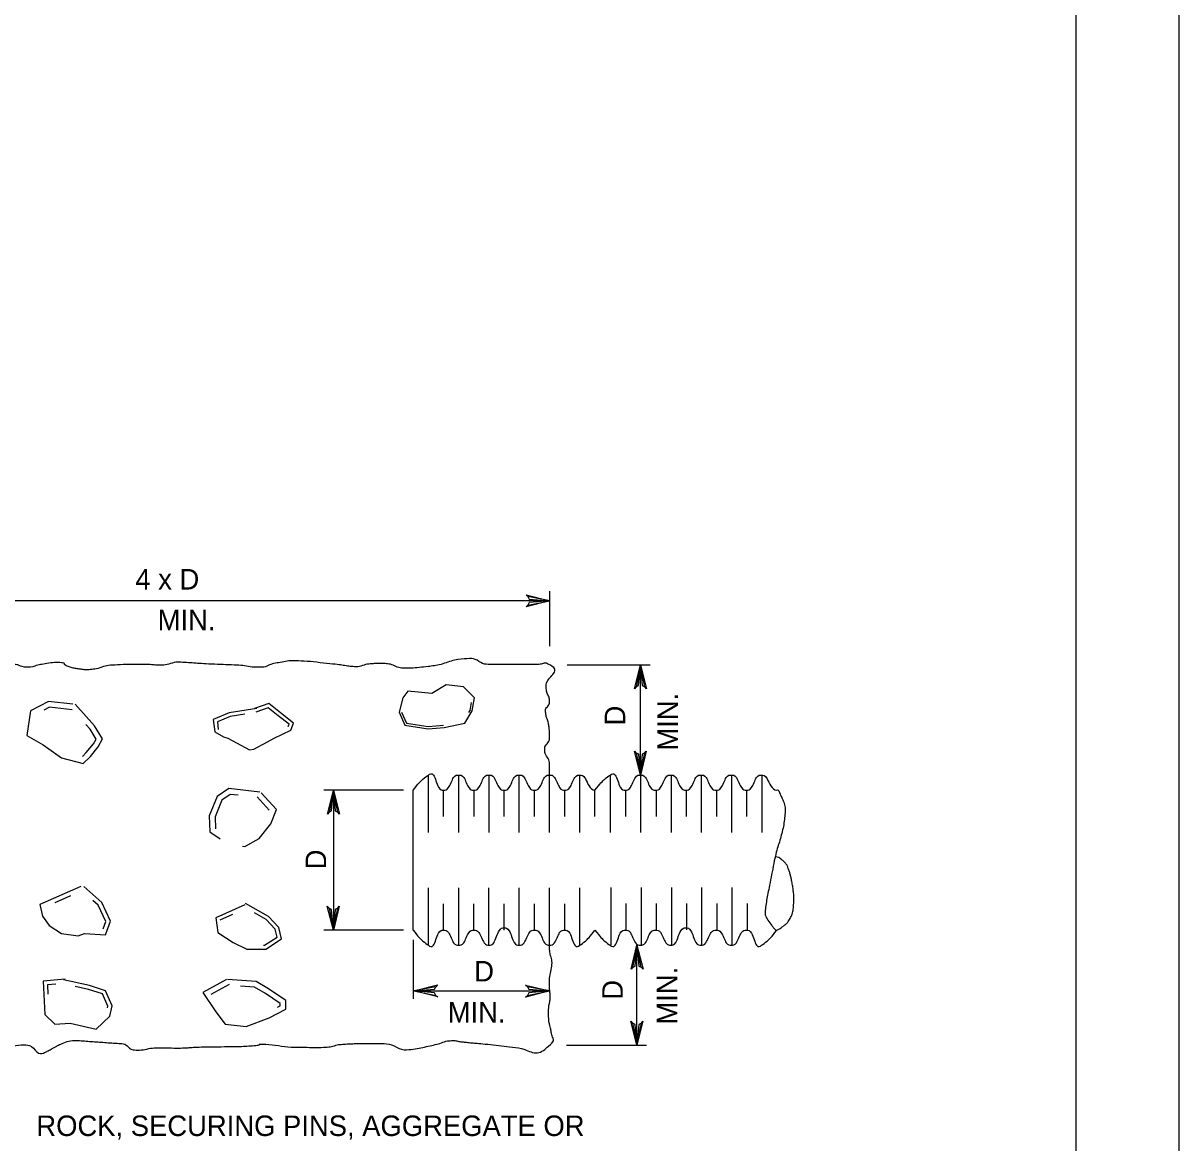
# Model space of a CAD drawing. Extents: x 636462 to 637367, y 299944 to 300538.
# Drawn here: x 637133.8 to 637302.9, y 300210.9 to 300374.7 of the extents above; entities that cross this region are included whole.
import ezdxf

# ---------------------------------------------------------------- set-up
doc = ezdxf.new("R2010")
doc.units = 0
for name, color, linetype in [('1', 7, 'Continuous'), ('Default', 7, 'Continuous'), ('PLT-BNDY', 7, 'Continuous')]:
    doc.layers.add(name, color=color, linetype=linetype)

# ---------------------------------------------------------------- blocks, each defined once
blk = doc.blocks.new('SC9446')
at = {"layer": 'Default'}
blk.add_line((0, 0), (0, 0), dxfattribs=at)

msp = doc.modelspace()

# ---------------------------------------------------------------- linework, layer by layer
at = {"layer": '1'}
msp.add_lwpolyline([(637287.91, 299959.45), (637287.91, 300523.45), (636501.91, 300523.45), (636501.91, 299959.45), (637287.91, 299959.45), (637287.91, 299985.81), (637087.91, 299985.81), (637087.91, 300050.49), (637287.91, 300050.49), (637287.91, 300079.45), (637087.91, 300079.45), (637087.91, 299959.45), (637166.72, 299959.45), (637166.72, 299985.81), (637166.72, 299959.45), (637243.72, 299959.45), (637243.72, 299985.81), (637243.72, 299973.49), (637287.91, 299973.49)], dxfattribs=at)
at = {"layer": 'Default'}
for p, q in [((637210.91, 300283.57), (637210.91, 300291.6)), ((637210.91, 300290.19), (637109.32, 300290.19)), ((637213.45, 300280.83), (637225.56, 300280.83)), ((637224.15, 300264.71), (637224.15, 300280.83)), ((637199.04, 300273.87), (637199.27, 300274.26)), ((637199.24, 300274.16), (637199.43, 300275.33)), ((637193.13, 300256.29), (637193.13, 300264.71)), ((637197.56, 300256.29), (637197.56, 300264.71)), ((637201.99, 300264.71), (637201.99, 300256.29)), ((637206.42, 300256.29), (637206.42, 300264.71)), ((637210.85, 300256.29), (637210.85, 300264.71)), ((637215.29, 300256.29), (637215.29, 300264.71)), ((637219.79, 300256.3), (637219.79, 300264.72)), ((637224.22, 300256.3), (637224.22, 300264.72)), ((637228.65, 300264.72), (637228.65, 300256.3)), ((637233.08, 300256.3), (637233.08, 300264.72)), ((637237.51, 300256.3), (637237.51, 300264.72)), ((637241.95, 300256.3), (637241.95, 300264.72)), ((637189.5, 300262.49), (637177.82, 300262.49)), ((637179.23, 300262.49), (637179.23, 300242.02)), ((637190.91, 300242.02), (637190.91, 300262.49)), ((637195.35, 300258.63), (637195.35, 300262.49)), ((637199.78, 300262.49), (637199.78, 300258.63)), ((637204.21, 300258.63), (637204.21, 300262.49)), ((637208.64, 300258.63), (637208.64, 300262.49)), ((637213.07, 300258.63), (637213.07, 300262.49)), ((637217.5, 300258.63), (637217.5, 300262.49)), ((637222, 300258.64), (637222, 300262.5)), ((637226.43, 300262.5), (637226.43, 300258.64)), ((637230.87, 300258.64), (637230.87, 300262.5)), ((637235.3, 300258.64), (637235.3, 300262.5)), ((637239.73, 300258.64), (637239.73, 300262.5)), ((637169.86, 300259.58), (637168.08, 300261.54)), ((637140.77, 300247.02), (637138.47, 300246.02)), ((637193.13, 300239.81), (637193.13, 300248.23)), ((637197.56, 300239.81), (637197.56, 300248.23)), ((637201.99, 300239.81), (637201.99, 300248.23)), ((637206.42, 300242.58), (637206.42, 300248.23)), ((637206.42, 300239.81), (637206.42, 300248.23)), ((637210.85, 300242.32), (637210.85, 300248.23)), ((637210.85, 300239.81), (637210.85, 300248.23)), ((637215.29, 300239.81), (637215.29, 300248.23)), ((637219.86, 300239.86), (637219.86, 300248.28)), ((637224.29, 300239.86), (637224.29, 300248.28)), ((637228.72, 300239.86), (637228.72, 300248.28)), ((637233.15, 300242.63), (637233.15, 300248.28)), ((637233.15, 300239.86), (637233.15, 300248.28)), ((637237.58, 300242.37), (637237.58, 300248.28)), ((637237.58, 300239.86), (637237.58, 300248.28)), ((637195.35, 300242.02), (637195.35, 300245.89)), ((637199.78, 300242.02), (637199.78, 300245.89)), ((637204.21, 300242.35), (637204.21, 300245.89)), ((637204.21, 300242.02), (637204.21, 300245.89)), ((637208.64, 300242.83), (637208.64, 300245.89)), ((637208.64, 300242.02), (637208.64, 300245.89)), ((637213.07, 300242.02), (637213.07, 300245.89)), ((637222.07, 300242.07), (637222.07, 300245.93)), ((637226.5, 300242.07), (637226.5, 300245.93)), ((637230.94, 300242.4), (637230.94, 300245.94)), ((637230.94, 300242.07), (637230.94, 300245.94)), ((637235.37, 300242.88), (637235.37, 300245.94)), ((637235.37, 300242.07), (637235.37, 300245.94)), ((637239.8, 300242.07), (637239.8, 300245.93)), ((637164.48, 300244.29), (637162.64, 300243.46)), ((637189.5, 300242.02), (637177.82, 300242.02)), ((637190.91, 300240.61), (637190.91, 300231.96)), ((637223.64, 300236.16), (637223.64, 300239.81)), ((637223.64, 300225.19), (637223.64, 300239.8)), ((637164.01, 300234.08), (637161.3, 300232.61)), ((637190.98, 300233.12), (637210.84, 300233.12)), ((637213.35, 300225.19), (637225.05, 300225.19))]:
    msp.add_line(p, q, dxfattribs=at)
for points in [[(637207.68, 300290.83), (637207.41, 300291.05), (637210.91, 300290.19), (637207.68, 300290.83), (637207.88, 300290.45), (637210.91, 300290.19), (637207.88, 300289.93), (637207.7, 300289.55), (637210.91, 300290.19), (637207.42, 300289.3), (637207.7, 300289.55)], [(637223.51, 300277.59), (637223.29, 300277.32), (637224.15, 300280.83), (637223.51, 300277.59), (637223.88, 300277.79), (637224.15, 300280.83), (637224.41, 300277.8), (637224.78, 300277.61), (637224.15, 300280.83), (637225.04, 300277.33), (637224.78, 300277.61)], [(637199.54, 300274.11), (637199.86, 300276.01), (637198.27, 300277.6), (637195.73, 300277.92), (637193.62, 300276.65), (637190.13, 300276.96), (637189.39, 300276.01), (637188.86, 300273.9), (637189.7, 300271.99), (637193.09, 300271.46), (637195.42, 300271.67), (637198.48, 300272.31), (637199.54, 300274.11)], [(637141.14, 300275.06), (637137.54, 300275.48), (637134.9, 300274.11), (637134.37, 300270.51), (637136.8, 300269.13), (637139.44, 300267.23), (637142.62, 300266.38), (637143.68, 300267.44), (637144.84, 300268.82), (637145.48, 300269.98), (637144.31, 300271.89), (637141.46, 300275.06)], [(637141.04, 300274.25), (637137.7, 300274.64), (637136.86, 300274.21)], [(637168.01, 300274.42), (637163.99, 300273.79), (637161.66, 300272.84), (637161.88, 300271.04), (637163.15, 300270.3), (637163.78, 300270.09), (637166.95, 300268.39), (637167.59, 300268.5), (637169.6, 300269.56), (637170.55, 300270.09), (637172.99, 300271.25), (637173.41, 300272.31), (637171.5, 300273.79), (637169.81, 300275.17), (637167.7, 300274.42)], [(637172.62, 300271.82), (637172.75, 300272.13), (637171.16, 300273.36), (637169.7, 300274.55), (637167.88, 300273.91)], [(637166.3, 300273.6), (637164.14, 300273.26), (637162.26, 300272.49), (637162.39, 300271.37)], [(637189.18, 300273.92), (637189.92, 300272.27), (637193.1, 300271.78), (637195.32, 300271.98)], [(637142.52, 300267.44), (637143.08, 300268), (637144.16, 300269.28), (637144.53, 300269.96), (637143.65, 300271.39), (637143.03, 300272.09)], [(637224.79, 300267.94), (637225.01, 300268.21), (637224.15, 300264.71), (637224.79, 300267.94), (637224.41, 300267.74), (637224.15, 300264.71), (637223.89, 300267.74), (637223.51, 300267.92), (637224.15, 300264.71), (637223.26, 300268.2), (637223.51, 300267.92)], [(637168.48, 300262.21), (637163.93, 300262.74), (637162.24, 300261.58), (637161.08, 300258.72), (637161.18, 300256.39), (637162.67, 300255.38)], [(637178.59, 300259.26), (637178.37, 300258.99), (637179.23, 300262.49), (637178.59, 300259.26), (637178.96, 300259.46), (637179.23, 300262.49), (637179.49, 300259.46), (637179.86, 300259.28), (637179.23, 300262.49), (637180.12, 300259), (637179.86, 300259.28)], [(637165.3, 300261.74), (637164.15, 300261.87), (637162.92, 300261.03), (637161.92, 300258.57), (637162, 300256.85)], [(637165.92, 300254.32), (637166.26, 300254.27), (637168.38, 300255.44), (637170.07, 300257.55), (637170.92, 300259.67), (637168.69, 300262.1)], [(637142.3, 300248.4), (637136.27, 300245.75), (637136.7, 300244.06), (637137.65, 300242.68), (637139.44, 300241.52), (637141.88, 300241.2), (637142.83, 300241.52), (637145.9, 300241.31), (637146.64, 300243.32), (637145.37, 300246.07), (637142.73, 300248.4)], [(637145.55, 300242.21), (637145.94, 300243.29), (637144.84, 300245.68), (637144.06, 300246.37)], [(637166.26, 300245.7), (637162.03, 300243.8), (637162.35, 300241.68), (637164.57, 300240.2), (637166.58, 300239.25), (637169.33, 300239.25), (637171.66, 300240.73), (637171.23, 300242.42), (637169.75, 300244.01), (637166.37, 300245.92)], [(637179.86, 300245.25), (637180.09, 300245.52), (637179.23, 300242.02), (637179.86, 300245.25), (637179.49, 300245.06), (637179.23, 300242.02), (637178.97, 300245.05), (637178.59, 300245.23), (637179.23, 300242.02), (637178.34, 300245.52), (637178.59, 300245.23)], [(637169.01, 300239.81), (637169.17, 300239.81), (637171.02, 300240.99), (637170.73, 300242.15), (637169.4, 300243.57), (637167.68, 300244.54)], [(637223, 300236.57), (637222.78, 300236.3), (637223.64, 300239.8), (637223, 300236.57), (637223.38, 300236.77), (637223.64, 300239.8), (637223.9, 300236.77), (637224.27, 300236.59), (637223.64, 300239.8), (637224.53, 300236.31), (637224.27, 300236.59)], [(637139.98, 300234.85), (637136.8, 300234.54), (637137.01, 300229.67), (637138.49, 300228.29), (637140.72, 300228.4), (637144.52, 300227.55), (637146.53, 300229.46), (637146.85, 300230.94), (637145.9, 300233.16), (637143.57, 300233.9), (637139.76, 300234.75)], [(637138.63, 300234.13), (637137.41, 300234.01), (637137.47, 300232.64)], [(637146.2, 300230.66), (637146.24, 300230.88), (637145.47, 300232.69), (637143.42, 300233.34), (637141.47, 300233.77)], [(637163.61, 300234.81), (637160.12, 300232.9), (637162.03, 300230.05), (637163.4, 300228.25), (637166.47, 300227.93), (637169.86, 300229.2), (637172.29, 300230.47), (637172.29, 300231.74), (637169.75, 300233.43), (637167.95, 300234.49), (637163.72, 300234.81)], [(637171.04, 300230.74), (637171.47, 300230.97), (637171.47, 300231.3), (637169.32, 300232.73), (637167.7, 300233.68), (637165.62, 300233.84)], [(637194.22, 300232.48), (637194.49, 300232.26), (637190.98, 300233.12), (637194.22, 300232.48), (637194.02, 300232.85), (637190.98, 300233.12), (637194.01, 300233.38), (637194.2, 300233.75), (637190.98, 300233.12), (637194.48, 300234.01), (637194.2, 300233.75)], [(637207.61, 300233.75), (637207.34, 300233.98), (637210.84, 300233.12), (637207.61, 300233.75), (637207.8, 300233.38), (637210.84, 300233.12), (637207.81, 300232.86), (637207.63, 300232.48), (637210.84, 300233.12), (637207.34, 300232.23), (637207.63, 300232.48)], [(637224.28, 300228.42), (637224.5, 300228.69), (637223.64, 300225.19), (637224.28, 300228.42), (637223.9, 300228.23), (637223.64, 300225.19), (637223.38, 300228.22), (637223.01, 300228.4), (637223.64, 300225.19), (637222.75, 300228.69), (637223.01, 300228.4)]]:
    msp.add_lwpolyline(points, dxfattribs=at)
for points in [[(637134.44, 300280.46), (637133.82, 300280.45), (637133.22, 300280.82), (637132.59, 300280.88), (637132.01, 300280.93), (637131.43, 300280.98), (637130.85, 300280.98), (637129.53, 300280.99), (637128.22, 300280.9), (637126.91, 300280.77), (637125.99, 300280.69), (637125.14, 300280.16), (637124.24, 300280.14), (637123.62, 300280.12), (637123.01, 300280.44), (637122.38, 300280.46), (637121.61, 300280.48), (637120.84, 300280.43), (637120.06, 300280.46), (637118.6, 300280.51), (637117.13, 300280.73), (637115.66, 300280.77), (637114.62, 300280.8), (637113.57, 300280.61), (637112.53, 300280.56), (637111.46, 300280.51), (637110.39, 300281.42), (637109.32, 300280.82), (637108.5, 300280.36), (637109.48, 300279.24), (637109.28, 300278.55), (637109.17, 300278.16), (637108.74, 300277.78), (637108.7, 300277.39), (637108.65, 300276.83), (637109.4, 300276.29), (637109.4, 300275.7), (637109.39, 300274.53), (637108.75, 300273.37), (637108.82, 300272.2), (637108.88, 300271.29), (637109.33, 300270.37), (637109.28, 300269.45), (637109.26, 300269), (637109.19, 300268.54), (637109.17, 300268.08), (637109.11, 300266.81), (637109.07, 300265.54), (637109.05, 300264.27), (637109.04, 300263.32), (637109.17, 300262.36), (637109.17, 300261.41), (637109.17, 300260.81), (637108.95, 300260.21), (637108.94, 300259.61), (637108.91, 300258.66), (637109.18, 300257.71), (637109.17, 300256.76), (637109.15, 300255.63), (637108.84, 300254.5), (637108.82, 300253.37), (637108.81, 300252.59), (637109.07, 300251.82), (637109.05, 300251.04), (637109.04, 300250.48), (637108.84, 300249.91), (637108.82, 300249.35), (637108.76, 300248.05), (637109.11, 300246.73), (637109.05, 300245.43), (637109.03, 300244.86), (637108.73, 300244.31), (637108.7, 300243.74), (637108.65, 300242.58), (637109.09, 300241.41), (637109.05, 300240.25), (637109.02, 300239.23), (637108.53, 300238.21), (637108.59, 300237.18), (637108.7, 300235.21), (637109.17, 300233.24), (637109.28, 300231.26), (637109.34, 300230.34), (637109.36, 300229.42), (637109.4, 300228.51), (637109.44, 300227.4), (637108.56, 300226.3), (637109.32, 300225.19), (637109.81, 300224.48), (637110.86, 300225.81), (637111.6, 300225.65), (637112.38, 300225.48), (637113.12, 300225), (637113.92, 300224.91), (637115.9, 300224.69), (637117.96, 300224.62), (637119.95, 300224.7), (637121.54, 300224.76), (637123.13, 300225.58), (637124.7, 300225.44)], [(637210.86, 300264.71), (637210.86, 300265.2), (637210.85, 300265.68), (637210.85, 300266.17), (637210.84, 300266.94), (637210.18, 300267.66), (637210.15, 300268.39), (637210.13, 300269), (637210.83, 300269.58), (637210.85, 300270.19), (637210.86, 300270.77), (637210.82, 300271.4), (637210.73, 300271.99), (637210.64, 300272.63), (637210.34, 300273.27), (637210.27, 300273.9), (637210.21, 300274.43), (637210.86, 300274.95), (637210.85, 300275.48), (637210.84, 300276.08), (637210.46, 300276.68), (637210.38, 300277.28), (637210.24, 300278.44), (637212.17, 300280.07), (637210.86, 300280.82), (637210.24, 300281.19), (637209.62, 300280.88), (637208.99, 300280.88), (637207.91, 300280.88), (637206.83, 300280.88), (637205.75, 300280.88), (637204.55, 300280.88), (637203.35, 300280.88), (637202.15, 300280.88), (637201.03, 300280.88), (637200, 300281.77), (637198.91, 300281.73), (637196.95, 300281.65), (637194.98, 300280.79), (637192.99, 300280.56), (637191.81, 300280.43), (637190.58, 300280.29), (637189.4, 300280.35), (637188.57, 300280.39), (637187.8, 300280.92), (637186.96, 300280.98), (637186.28, 300281.04), (637185.56, 300281.03), (637184.88, 300280.98), (637183.95, 300280.92), (637183.03, 300280.49), (637182.1, 300280.56), (637181.28, 300280.62), (637180.47, 300280.79), (637179.66, 300280.88), (637177.77, 300281.08), (637175.87, 300281.31), (637173.98, 300281.41), (637172.97, 300281.46), (637171.97, 300281.25), (637170.96, 300281.09), (637170.09, 300280.95), (637169.29, 300280.46), (637168.41, 300280.46), (637167.34, 300280.46), (637166.25, 300280.72), (637165.17, 300280.77), (637163.51, 300280.85), (637161.84, 300280.91), (637160.18, 300280.98), (637159.1, 300281.04), (637158.02, 300281.15), (637156.94, 300281.2), (637155.92, 300281.24), (637154.93, 300280.77), (637153.92, 300280.77), (637153.19, 300280.77), (637152.45, 300280.87), (637151.72, 300280.88), (637150.09, 300280.9), (637148.47, 300280.87), (637146.85, 300280.77), (637145.82, 300280.71), (637144.85, 300280.24), (637143.83, 300280.14), (637143.15, 300280.07), (637142.44, 300280.15), (637141.75, 300280.24), (637141.14, 300280.33), (637140.56, 300280.53), (637140.01, 300280.77), (637139.88, 300280.83), (637139.91, 300281.07), (637139.78, 300281.09), (637138.72, 300281.22), (637137.59, 300281.05), (637136.53, 300280.88), (637135.83, 300280.77), (637135.14, 300280.46), (637134.44, 300280.46)], [(637190.91, 300262.49), (637191.65, 300263.48), (637192.39, 300264.19), (637193.13, 300264.71), (637193.87, 300265.23), (637194.61, 300262.49), (637195.35, 300262.49), (637196.08, 300262.49), (637196.82, 300264.71), (637197.56, 300264.71), (637198.3, 300264.71), (637199.04, 300262.49), (637199.78, 300262.49), (637200.51, 300262.49), (637201.25, 300264.71), (637201.99, 300264.71), (637202.73, 300264.71), (637203.47, 300262.49), (637204.21, 300262.49), (637204.95, 300262.49), (637205.68, 300264.71), (637206.42, 300264.71), (637207.16, 300264.71), (637207.9, 300262.49), (637208.64, 300262.49), (637209.38, 300262.49), (637210.12, 300264.71), (637210.85, 300264.71), (637211.59, 300264.71), (637212.33, 300262.49), (637213.07, 300262.49), (637213.81, 300262.49), (637214.55, 300264.71), (637215.29, 300264.71), (637216.03, 300264.71), (637216.76, 300262.49), (637217.5, 300262.49)], [(637217.5, 300262.49), (637218.24, 300263.48), (637218.98, 300264.18), (637219.72, 300264.71), (637220.46, 300265.23), (637221.19, 300262.49), (637221.93, 300262.49), (637222.67, 300262.49), (637223.41, 300264.71), (637224.15, 300264.71), (637224.89, 300264.71), (637225.62, 300262.49), (637226.36, 300262.49), (637227.1, 300262.49), (637227.84, 300264.71), (637228.58, 300264.71), (637229.32, 300264.71), (637230.06, 300262.49), (637230.79, 300262.49), (637231.53, 300262.49), (637232.27, 300264.71), (637233.01, 300264.71), (637233.75, 300264.71), (637234.49, 300262.49), (637235.23, 300262.49), (637235.97, 300262.49), (637236.7, 300264.71), (637237.44, 300264.71), (637238.18, 300264.71), (637238.92, 300262.49), (637239.66, 300262.49), (637240.4, 300262.49), (637241.14, 300264.71), (637241.87, 300264.71), (637242.61, 300264.71), (637243.35, 300262.49), (637244.09, 300262.49)], [(637244.09, 300262.49), (637244.3, 300262.69), (637244.66, 300261.77), (637244.86, 300261.3), (637245.2, 300260.53), (637245.35, 300259.75), (637245.28, 300258.98), (637245.19, 300257.95), (637245.02, 300256.93), (637244.75, 300255.91), (637244.49, 300254.9), (637244.12, 300253.95), (637243.91, 300252.94), (637243.56, 300251.36), (637243.27, 300249.77), (637242.95, 300248.18), (637242.75, 300247.16), (637242.56, 300246.14), (637242.43, 300245.12), (637242.31, 300244.26), (637242.78, 300243.48), (637243.38, 300242.68), (637243.6, 300242.38), (637243.84, 300242.07), (637244.09, 300242.02)], [(637244.09, 300242.02), (637244.38, 300242.14), (637244.61, 300242.29), (637244.86, 300242.47), (637245.27, 300242.78), (637245.64, 300243.07), (637245.92, 300243.53), (637246.33, 300244.2), (637246.49, 300244.91), (637246.55, 300245.65), (637246.6, 300246.24), (637246.62, 300246.85), (637246.55, 300247.45), (637246.48, 300248.12), (637246.37, 300248.79), (637246.23, 300249.45), (637246.13, 300249.96), (637245.99, 300250.45), (637245.81, 300250.94), (637245.65, 300251.37), (637245.46, 300251.73), (637245.07, 300252.1), (637244.69, 300252.45), (637244.3, 300252.73), (637243.91, 300252.74)], [(637190.91, 300242.02), (637191.65, 300241.04), (637192.39, 300240.33), (637193.13, 300239.81), (637193.87, 300239.28), (637194.61, 300242.02), (637195.35, 300242.02), (637196.08, 300242.02), (637196.82, 300239.81), (637197.56, 300239.81), (637198.3, 300239.81), (637199.04, 300242.01), (637199.78, 300242.02), (637200.51, 300242.04), (637201.31, 300239.81), (637201.99, 300239.81), (637202.73, 300239.81), (637203.47, 300242.35), (637204.21, 300242.35), (637204.95, 300242.35), (637205.66, 300239.81), (637206.42, 300239.81), (637207.14, 300239.81), (637207.9, 300242.04), (637208.64, 300242.02), (637209.38, 300242.01), (637210.12, 300239.81), (637210.85, 300239.81), (637211.59, 300239.81), (637212.33, 300242.02), (637213.07, 300242.02), (637213.81, 300242.02), (637214.55, 300239.28), (637215.29, 300239.81), (637216.03, 300240.33), (637216.76, 300241.04), (637217.5, 300242.02)], [(637217.5, 300242.02), (637218.24, 300241.04), (637218.98, 300240.33), (637219.72, 300239.81), (637220.46, 300239.28), (637221.19, 300242.02), (637221.93, 300242.02), (637222.67, 300242.02), (637223.41, 300239.81), (637224.15, 300239.81), (637224.89, 300239.81), (637225.62, 300242.01), (637226.36, 300242.02), (637227.1, 300242.04), (637227.89, 300239.81), (637228.58, 300239.81), (637229.32, 300239.81), (637230.06, 300242.35), (637230.79, 300242.35), (637231.53, 300242.35), (637232.24, 300239.81), (637233.01, 300239.81), (637233.72, 300239.81), (637234.49, 300242.04), (637235.23, 300242.02), (637235.97, 300242.01), (637236.7, 300239.81), (637237.44, 300239.81), (637238.18, 300239.81), (637238.92, 300242.02), (637239.66, 300242.02), (637240.4, 300242.02), (637241.14, 300239.28), (637241.87, 300239.81), (637242.61, 300240.33), (637243.35, 300241.04), (637244.09, 300242.02)], [(637210.73, 300229.03), (637210.7, 300229.56), (637210.7, 300230.1), (637210.73, 300230.62), (637210.77, 300231.15), (637210.94, 300231.68), (637210.94, 300232.21), (637210.94, 300232.77), (637210.84, 300233.34), (637210.84, 300233.9), (637210.84, 300234.32), (637210.84, 300234.75), (637210.84, 300235.17), (637211.47, 300237.8), (637210.84, 300238.26), (637210.85, 300239.81)], [(637124.7, 300225.44), (637125.1, 300225.4), (637125.46, 300225.19), (637125.86, 300225.12), (637126.98, 300224.92), (637128.1, 300224.77), (637129.22, 300224.7), (637130.81, 300224.59), (637132.4, 300225.21), (637133.98, 300225.23), (637135.08, 300225.24), (637136.13, 300223.7), (637137.11, 300224.17), (637137.38, 300224.3), (637137.65, 300224.45), (637137.92, 300224.59), (637138.31, 300224.8), (637138.68, 300225.02), (637139.08, 300225.23), (637140, 300225.69), (637141.07, 300225.93), (637142.09, 300225.86), (637143.06, 300225.79), (637144.03, 300225.72), (637144.99, 300225.65), (637146.04, 300225.58), (637147.08, 300225.51), (637148.12, 300225.44), (637148.93, 300225.38), (637149.52, 300224.5), (637150.33, 300224.49), (637151.4, 300224.47), (637152.48, 300224.79), (637153.57, 300224.8), (637154.89, 300224.82), (637156.2, 300224.75), (637157.52, 300224.8), (637158.13, 300224.83), (637158.75, 300224.89), (637159.37, 300224.91), (637161.34, 300224.98), (637163.31, 300224.97), (637165.28, 300225.01), (637166.33, 300225.04), (637167.37, 300225.11), (637168.41, 300225.23), (637168.45, 300225.23), (637168.37, 300225.33), (637168.41, 300225.33), (637170.26, 300225.34), (637172.12, 300224.93), (637173.98, 300224.91), (637175.37, 300224.89), (637176.77, 300224.82), (637178.15, 300224.91), (637178.98, 300224.96), (637179.76, 300225.28), (637180.59, 300225.33), (637181.44, 300225.39), (637182.29, 300225.42), (637183.14, 300225.44), (637184.18, 300225.46), (637185.24, 300225.46), (637186.27, 300225.44), (637187.75, 300225.41), (637189.21, 300224.4), (637190.67, 300224.59), (637191.76, 300224.73), (637192.84, 300224.99), (637193.92, 300225.23), (637194.82, 300225.42), (637195.68, 300225.83), (637196.59, 300225.86), (637197.16, 300225.88), (637197.74, 300225.7), (637198.33, 300225.65), (637199.1, 300225.58), (637199.87, 300225.51), (637200.65, 300225.44), (637202.23, 300225.29), (637203.81, 300225.08), (637205.4, 300224.91), (637207.21, 300224.71), (637209.08, 300223.62), (637210.86, 300225.19), (637211.6, 300225.84), (637211.18, 300226.56), (637211.08, 300227.24), (637210.99, 300227.83), (637210.77, 300228.43), (637210.73, 300229.03)]]:
    msp.add_open_spline(points, degree=3, dxfattribs=at)
at = {"layer": 'PLT-BNDY'}
msp.add_lwpolyline([(636461.91, 300538.45), (637302.91, 300538.45), (637302.91, 299944.45), (636461.91, 299944.45)], close=True, dxfattribs=at)

# ---------------------------------------------------------------- block references
at = {"layer": 'Default', "xscale": 2.2030652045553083, "yscale": 2.2030652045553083}
for p in [(637201.99, 300248.23), (637228.72, 300248.28)]:
    msp.add_blockref('SC9446', p, dxfattribs=at)

# ---------------------------------------------------------------- texts
at = {"layer": 'Default'}
for s, height, p in [('4 x D', 2.998, (637150.26, 300291.84)), ('MIN.', 2.998, (637153.52, 300285.87)), ('D', 3, (637199.83, 300234.51)), ('MIN.', 2.998, (637195.96, 300228.51)), ('ROCK, SECURING PINS, AGGREGATE OR', 2.998, (637135.78, 300211.91))]:
    msp.add_text(s, height=height, dxfattribs=at).set_placement(p)
for s, height, p in [('MIN.', 2.998, (637229.64, 300268.28)), ('D', 3, (637221.92, 300271.96)), ('D', 3, (637178.17, 300250.91)), ('MIN.', 2.998, (637229.54, 300228.21)), ('D', 3, (637221.56, 300231.84))]:
    msp.add_text(s, height=height, rotation=90, dxfattribs=at).set_placement(p)

doc.saveas('drawing.dxf')
